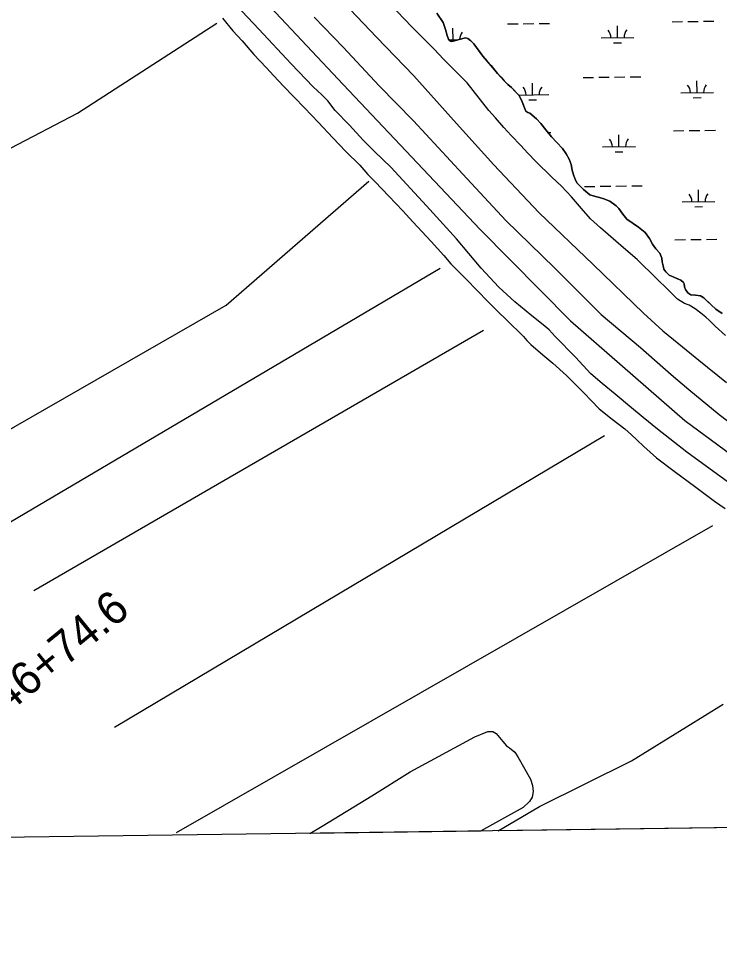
# Model space of a CAD drawing. Extents: x 3753511 to 3791668, y 379550 to 405377.
# Drawn here: x 3780816 to 3782955, y 384970 to 387781 of the extents above; entities that cross this region are included whole.
import ezdxf

# ---------------------------------------------------------------- set-up
doc = ezdxf.new("R2010")
doc.units = 0
for name, color, linetype in [('V-GRID-FRAM', 7, 'Continuous'), ('V-LEVE-TOET', 7, 'Continuous'), ('V-ROAD-CNTR', 7, 'Continuous'), ('V-SITE-VEGE', 7, 'Continuous'), ('V-SURV-IDEN', 7, 'Continuous'), ('V-TOPO-SHOR', 7, 'Continuous'), ('V-WETL-SWMP', 7, 'Continuous')]:
    doc.layers.add(name, color=color, linetype=linetype)

msp = doc.modelspace()

# ---------------------------------------------------------------- linework, layer by layer
at = {"layer": 'V-GRID-FRAM'}
msp.add_lwpolyline([(3757521.7, 403151.1), (3789298.9, 403581), (3789552.8, 385400.3), (3757759.7, 384970.3), (3757521.7, 403151.1)], dxfattribs=at)
at = {"layer": 'V-LEVE-TOET'}
for points in [[(3781809, 387828.6), (3781907.9, 387724.2), (3782022, 387606), (3782152.8, 387460.2), (3782266.2, 387334.7), (3782404, 387188.9), (3782569.8, 387030.2), (3782722.7, 386881.8), (3782782.6, 386828.1), (3782831.2, 386787.9), (3782891.9, 386737.8), (3782976.6, 386669.6)], [(3781717.7, 387785), (3781806.9, 387693.3), (3781916.3, 387575.5), (3782021.4, 387468.1), (3782171.4, 387305.4), (3782303.4, 387164.6), (3782451.6, 387020), (3782594.1, 386877.3), (3782713.8, 386777), (3782807.6, 386695), (3782861.6, 386649.1), (3782954.1, 386572.1), (3783004.6, 386533.8)]]:
    msp.add_lwpolyline(points, dxfattribs=at)
at = {"layer": 'V-ROAD-CNTR'}
msp.add_lwpolyline([(3780277.5, 389351.6), (3780565.4, 389006.4), (3780889.7, 388616.6), (3781215.6, 388223.9), (3781473.8, 387934.5), (3781806.9, 387579.9), (3782224.7, 387137.4), (3782500.5, 386858.1), (3782848.9, 386553.8), (3783232.9, 386271.6)], dxfattribs=at)
at = {"layer": 'V-SITE-VEGE'}
for p, q in [((3782686.8, 385515.7), (3782966.1, 385688.8)), ((3782011, 385481.9), (3782208.7, 385588.8)), ((3782208.7, 385588.8), (3782248.2, 385605.5)), ((3782248.2, 385605.5), (3782263.3, 385604.9)), ((3782263.3, 385604.9), (3782273.6, 385599.5)), ((3782273.6, 385599.5), (3782293.6, 385574.4)), ((3782293.6, 385574.4), (3782305.3, 385561.4)), ((3782305.3, 385561.4), (3782314.3, 385555.3)), ((3782314.3, 385555.3), (3782330.8, 385541.8)), ((3782330.8, 385541.8), (3782339.8, 385528.2)), ((3782339.8, 385528.2), (3782378.6, 385460)), ((3782405.9, 385376.1), (3782686.8, 385515.7)), ((3781893.8, 385409.2), (3782011, 385481.9)), ((3782378.6, 385460), (3782384.2, 385440.2)), ((3782384.2, 385440.2), (3782386.4, 385422.4)), ((3782386.4, 385422.4), (3782383.1, 385405.3)), ((3781742.6, 385316.4), (3781893.8, 385409.2)), ((3782375.7, 385391.6), (3782356, 385373)), ((3782383.1, 385405.3), (3782375.7, 385391.6)), ((3782279.3, 385302), (3782405.9, 385376.1)), ((3782356, 385373), (3782281, 385332)), ((3782281, 385332), (3782225.3, 385301.2)), ((3781705.3, 385294.2), (3781742.6, 385316.4)), ((3782225.3, 385301.2), (3781705.3, 385294.2)), ((3783175.3, 385314.1), (3782279.3, 385302))]:
    msp.add_line(p, q, dxfattribs=at)
at = {"layer": 'V-TOPO-SHOR'}
for p, q in [((3780323.5, 385968.8), (3782102.5, 387019.1)), ((3780862.9, 386035), (3782234.9, 386829.9)), ((3781108.9, 385618.6), (3782604, 386508.1)), ((3781298.2, 385296.9), (3782935.2, 386233.7))]:
    msp.add_line(p, q, dxfattribs=at)
for points in [[(3781902.6, 387374.6), (3781868.1, 387410), (3781825.9, 387455.6), (3781781.7, 387500.5), (3781759.6, 387529.1), (3781741.6, 387547.5), (3781715.4, 387572), (3781647.7, 387642.8), (3781548.8, 387748.3), (3781430, 387875.7), (3781298, 388022.1)], [(3782184.5, 387584.2), (3782140.3, 387629.2), (3782112.7, 387657.1), (3782084.3, 387687), (3782045, 387726.5), (3782018, 387753), (3781991.8, 387781), (3781956.5, 387818.4), (3781928.9, 387849), (3781905.4, 387872.2), (3781879.9, 387896), (3781855.7, 387919.8), (3781832.2, 387946.4), (3781812.8, 387971.6), (3781794.8, 387997.5), (3781782.3, 388010.5)], [(3781438.2, 387781.8), (3781470, 387743.6), (3781498.4, 387712.3), (3781533.7, 387670.8), (3781571.7, 387631.3), (3781595.2, 387605.4), (3781624.9, 387574.1), (3781656.6, 387540.7), (3781688.4, 387508.7), (3781731.3, 387463.8), (3781775.5, 387416.8), (3781814.9, 387375.3), (3781857, 387333.1), (3781881.9, 387305.2), (3781904, 387282), (3781946.1, 387239.1), (3781989, 387194.2), (3782018.7, 387160.8), (3782075.4, 387100.2), (3782114.1, 387057.3), (3782135.5, 387032.1), (3782181.8, 386985.1), (3782248.8, 386916.4), (3782279.9, 386885.8), (3782304.1, 386862), (3782322, 386844.3), (3782339.3, 386827.9), (3782357.2, 386810.2), (3782366.9, 386798.7), (3782379.3, 386785.7), (3782402.1, 386766.7), (3782422.1, 386749), (3782446.3, 386728.6), (3782488.4, 386691.9), (3782518.1, 386662), (3782541.6, 386637.5), (3782563.7, 386615), (3782587.8, 386589.8), (3782627.2, 386557.9), (3782665.8, 386528.7), (3782686.5, 386510.3), (3782702.4, 386494.7), (3782723.7, 386474.9), (3782763.1, 386440.3), (3782816.9, 386399.5), (3782883, 386350.7), (3782940.3, 386307.9), (3782972, 386285.5)], [(3782092.2, 387797.5), (3782111.6, 387768.1), (3782119.3, 387746.9), (3782124.2, 387728.5), (3782127.7, 387717.5), (3782131.2, 387713.4), (3782134.6, 387711.4), (3782138.7, 387710.7), (3782146.3, 387712.8), (3782160.6, 387717.1), (3782179.8, 387721.3), (3782187.3, 387719.3), (3782196.3, 387712.5), (3782205.3, 387703), (3782233, 387665.5), (3782246.1, 387650.5), (3782257.9, 387636.9), (3782269.6, 387623.3), (3782277.9, 387613), (3782288.3, 387601.5), (3782298, 387590.6), (3782309, 387579.7), (3782320.1, 387570.2), (3782331.8, 387557.9), (3782342.2, 387547), (3782350.5, 387532), (3782354.7, 387521), (3782359.6, 387508.1), (3782364.5, 387498.5), (3782370, 387493.7), (3782376.2, 387491.7), (3782396.2, 387474.7), (3782410, 387460.4), (3782425.2, 387440.7), (3782441.9, 387420.2), (3782458.4, 387402.5), (3782476.4, 387384.1), (3782486.8, 387367.8), (3782495.8, 387351.4), (3782502.1, 387335), (3782505.7, 387318.5), (3782509.2, 387303.5), (3782515.5, 387287.8), (3782521.1, 387278.2), (3782529.3, 387270), (3782540.4, 387259.1), (3782559.7, 387242.8), (3782576.9, 387237.5), (3782589.3, 387234.1)], [(3779727.4, 386829.9), (3780995.4, 387492.2), (3781421.2, 387766.6)], [(3782973.1, 386814), (3782942.1, 386841.8), (3782924.8, 386859.5), (3782913.8, 386869.7), (3782898.6, 386881.3), (3782880.7, 386894.9), (3782862.1, 386906.4), (3782848.3, 386911.1), (3782827, 386924.6), (3782798, 386952.5), (3782762.8, 386987.2), (3782703.4, 387045.8), (3782662, 387081.1), (3782615, 387121.9), (3782591.6, 387141.6), (3782561.2, 387169.5), (3782534.2, 387200.8), (3782503.8, 387236.9), (3782473.4, 387268.9), (3782443, 387296.8), (3782394.7, 387344.5), (3782369.8, 387369.6), (3782348.4, 387392.8), (3782319.4, 387424.1), (3782296.6, 387448.6), (3782271, 387477.9), (3782251.6, 387499.7), (3782184.5, 387584.2)], [(3782982.8, 386364.8), (3782855.2, 386457.1), (3782766.3, 386527.8), (3782722.1, 386563.1), (3782687, 386593), (3782636.6, 386634.5), (3782596.6, 386667.1), (3782562.1, 386696.3), (3782515.4, 386747), (3782453.9, 386810.3), (3782435.2, 386830.7), (3782417.3, 386846.3), (3782382.8, 386873.5), (3782330.4, 386916.3), (3782281.4, 386960.5), (3782227.5, 387019.1), (3782152.8, 387108.3), (3782060.9, 387209.1), (3781952.3, 387327.6), (3781902.6, 387374.6)], [(3780162.7, 386167.5), (3781449.6, 386905.6), (3781884.8, 387284.1)], [(3782589.3, 387234.1), (3782602.3, 387230.1), (3782620.2, 387223.4), (3782639.5, 387209.1), (3782647.8, 387201), (3782659.6, 387183.9), (3782672.7, 387168.9), (3782707.8, 387144.5), (3782727.8, 387128.2), (3782741, 387109.1), (3782750.7, 387092), (3782761.1, 387077.7), (3782772.9, 387064.8), (3782779.2, 387049.1), (3782780.6, 387038.8), (3782782.8, 387025.8), (3782785.6, 387016.2), (3782791.1, 387007.3), (3782801.5, 386997.8), (3782813.9, 386992.4), (3782824.9, 386987.7), (3782837.2, 386982.3), (3782845.5, 386975.5), (3782847.6, 386971.4), (3782848.4, 386962.5), (3782851.2, 386953.6), (3782858.1, 386944.1), (3782867.7, 386938), (3782881.5, 386936.7), (3782896.6, 386934.7), (3782907.6, 386928.7), (3782917.9, 386918.5), (3782929.7, 386906.9), (3782944.2, 386894), (3782963.5, 386881.1)]]:
    msp.add_lwpolyline(points, dxfattribs=at)
at = {"layer": 'V-WETL-SWMP'}
for p, q in [((3782111.6, 387768.1), (3782092.2, 387797.5)), ((3782119.3, 387746.9), (3782111.6, 387768.1)), ((3782124.2, 387728.5), (3782119.3, 387746.9)), ((3782141.9, 387715.4), (3782141.4, 387751.4)), ((3782308.4, 387764.1), (3782340.3, 387764.5)), ((3782356.3, 387764.7), (3782388.3, 387765.2)), ((3782404.3, 387765.4), (3782436.3, 387765.8)), ((3782643.8, 387722.2), (3782643.3, 387758.2)), ((3782810.2, 387770.9), (3782842.2, 387771.3)), ((3782858.2, 387771.5), (3782890.2, 387771.9)), ((3782906.2, 387772.2), (3782938.2, 387772.6)), ((3782127.7, 387717.5), (3782124.2, 387728.5)), ((3782131.2, 387713.4), (3782127.7, 387717.5)), ((3782160.6, 387717.1), (3782138.7, 387710.7)), ((3782179.8, 387721.3), (3782160.6, 387717.1)), ((3782187.4, 387719.3), (3782179.8, 387721.3)), ((3782196.3, 387712.5), (3782187.4, 387719.3)), ((3782593.8, 387721.5), (3782693.8, 387722.8)), ((3782129.7, 387715.2), (3782155.5, 387715.6)), ((3782134.6, 387711.4), (3782131.2, 387713.4)), ((3782138.7, 387710.7), (3782134.6, 387711.4)), ((3782191.7, 387716.1), (3782191.9, 387716.1)), ((3782205.3, 387703), (3782196.3, 387712.5)), ((3782233, 387665.5), (3782205.3, 387703)), ((3782632, 387706.6), (3782656, 387706.9)), ((3782246.1, 387650.5), (3782233, 387665.5)), ((3782269.6, 387623.3), (3782246.1, 387650.5)), ((3782277.9, 387613), (3782269.6, 387623.3)), ((3782298, 387590.6), (3782277.9, 387613)), ((3782309, 387579.7), (3782298, 387590.6)), ((3782320.1, 387570.2), (3782309, 387579.7)), ((3782384.7, 387547.8), (3782384.2, 387583.8)), ((3782538.6, 387600.7), (3782570.6, 387601.1)), ((3782586.6, 387601.3), (3782618.6, 387601.7)), ((3782634.6, 387602), (3782666.6, 387602.4)), ((3782682.6, 387602.6), (3782714.6, 387603)), ((3782886.6, 387554.6), (3782886.1, 387590.6)), ((3782342.2, 387547), (3782320.1, 387570.2)), ((3782341.9, 387547.3), (3782434.7, 387548.5)), ((3782836.6, 387554), (3782936.5, 387555.3)), ((3782350.5, 387532), (3782342.2, 387547)), ((3782359.6, 387508.1), (3782350.5, 387532)), ((3782372.9, 387532.2), (3782396.9, 387532.6)), ((3782874.8, 387539), (3782898.8, 387539.4)), ((3782364.5, 387498.5), (3782359.6, 387508.1)), ((3782370, 387493.7), (3782364.5, 387498.5)), ((3782376.2, 387491.7), (3782370, 387493.7)), ((3782396.2, 387474.7), (3782376.2, 387491.7)), ((3782410, 387460.4), (3782396.2, 387474.7)), ((3782425.2, 387440.7), (3782410, 387460.4)), ((3782441.9, 387420.2), (3782425.2, 387440.7)), ((3782814.7, 387438.2), (3782846.7, 387438.6)), ((3782862.7, 387438.9), (3782894.7, 387439.3)), ((3782910.7, 387439.5), (3782942.7, 387439.9)), ((3782431.5, 387433), (3782440.8, 387433.2)), ((3782458.4, 387402.5), (3782441.9, 387420.2)), ((3782648.3, 387389.5), (3782647.8, 387425.5)), ((3782476.4, 387384.1), (3782458.4, 387402.5)), ((3782486.8, 387367.8), (3782476.4, 387384.1)), ((3782598.3, 387388.9), (3782698.3, 387390.2)), ((3782495.8, 387351.4), (3782486.8, 387367.8)), ((3782502.1, 387335), (3782495.8, 387351.4)), ((3782636.5, 387373.9), (3782660.5, 387374.3)), ((3782505.7, 387318.5), (3782502.1, 387335)), ((3782509.2, 387303.5), (3782505.7, 387318.5)), ((3782515.5, 387287.8), (3782509.2, 387303.5)), ((3782521.1, 387278.2), (3782515.5, 387287.8)), ((3782540.4, 387259.1), (3782521.1, 387278.2)), ((3782543.1, 387268), (3782575.1, 387268.5)), ((3782591.1, 387268.7), (3782623.1, 387269.1)), ((3782639.1, 387269.3), (3782671.1, 387269.8)), ((3782687.1, 387270), (3782719.1, 387270.4)), ((3782559.7, 387242.8), (3782540.4, 387259.1)), ((3782576.9, 387237.5), (3782559.7, 387242.8)), ((3782891.1, 387222), (3782890.6, 387258)), ((3782589.3, 387234.1), (3782576.9, 387237.5)), ((3782602.3, 387230.1), (3782589.3, 387234.1)), ((3782620.2, 387223.4), (3782602.3, 387230.1)), ((3782639.5, 387209.1), (3782620.2, 387223.4)), ((3782841.1, 387221.3), (3782941, 387222.7)), ((3782647.8, 387201), (3782639.5, 387209.1)), ((3782659.6, 387183.9), (3782647.8, 387201)), ((3782672.7, 387168.9), (3782659.6, 387183.9)), ((3782879.3, 387206.4), (3782903.3, 387206.7)), ((3782707.8, 387144.5), (3782672.7, 387168.9)), ((3782727.8, 387128.2), (3782707.8, 387144.5)), ((3782741, 387109.1), (3782727.8, 387128.2)), ((3782750.7, 387092), (3782741, 387109.1)), ((3782819.2, 387105.6), (3782851.2, 387106)), ((3782867.2, 387106.2), (3782899.2, 387106.6)), ((3782915.2, 387106.9), (3782947.2, 387107.3)), ((3782761.1, 387077.7), (3782750.7, 387092)), ((3782772.9, 387064.8), (3782761.1, 387077.7)), ((3782779.2, 387049.1), (3782772.9, 387064.8)), ((3782780.6, 387038.8), (3782779.2, 387049.1)), ((3782782.8, 387025.8), (3782780.6, 387038.8)), ((3782785.6, 387016.2), (3782782.8, 387025.8)), ((3782791.1, 387007.3), (3782785.6, 387016.2)), ((3782801.5, 386997.8), (3782791.1, 387007.3)), ((3782837.2, 386982.3), (3782801.5, 386997.8)), ((3782845.5, 386975.5), (3782837.2, 386982.3)), ((3782847.6, 386971.4), (3782845.5, 386975.5)), ((3782848.4, 386962.5), (3782847.6, 386971.4)), ((3782851.2, 386953.6), (3782848.4, 386962.5)), ((3782858.1, 386944.1), (3782851.2, 386953.6)), ((3782867.7, 386938), (3782858.1, 386944.1)), ((3782881.5, 386936.7), (3782867.7, 386938)), ((3782896.6, 386934.7), (3782881.5, 386936.7)), ((3782907.6, 386928.7), (3782896.6, 386934.7)), ((3782929.7, 386906.9), (3782907.6, 386928.7)), ((3782944.2, 386894), (3782929.7, 386906.9)), ((3782963.5, 386881.1), (3782944.2, 386894))]:
    msp.add_line(p, q, dxfattribs=at)
for centre, start, end in [((3782588.5, 387721.9), 0.0029, 41.5465), ((3782699, 387723.4), 140.0029, 181.5465), ((3782197.2, 387716.6), 140.0029, 178.788), ((3782831.3, 387554.4), 0.0029, 41.5465), ((3782941.8, 387555.8), 140.0029, 181.5465), ((3782329.4, 387547.6), 0.0029, 41.5465), ((3782439.9, 387549.1), 140.0029, 181.5465), ((3782593, 387389.3), 0.0029, 41.5465), ((3782703.5, 387390.7), 140.0029, 181.5465), ((3782835.8, 387221.7), 0.0029, 41.5465), ((3782946.3, 387223.2), 140.0029, 181.5465), ((3782950.8, 386890.6), 140.0029, 140.6162)]:
    msp.add_arc(centre, 35.2, start, end, dxfattribs=at)

# ---------------------------------------------------------------- texts
at = {"layer": 'V-SURV-IDEN'}
msp.add_text('1846+74.6', height=100, rotation=39.1331, dxfattribs=at).set_placement((3780667.4, 385564.8))

doc.saveas('drawing.dxf')
